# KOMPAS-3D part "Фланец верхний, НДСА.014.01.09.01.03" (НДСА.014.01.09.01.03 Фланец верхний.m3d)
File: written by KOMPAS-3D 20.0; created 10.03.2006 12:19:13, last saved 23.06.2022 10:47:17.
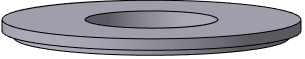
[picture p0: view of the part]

Document properties: Автор: Устинов А.В.; Организация: ЭСТО-Вакуум; Полное имя файла: C:\Users\cherbakova\Desktop\PLM\НДСА.014.01.09.01.03 Фланец верхний.m3d

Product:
- Part/product: Фланец верхний  | designation НДСА.014.01.09.01.03
    Материал: Сталь 20  ГОСТ 1050-88 (density 7820 kg/m3)
    Масса: 1.63755
    additional columns: <item xmlns="http://appius.ru/pdm" xmlns:xs="http://www.w3.org/2001/XMLSchema" x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; <item xmlns="http://appius.ru/pdm" xmlns:xs="http://www.w3.org/2001/XMLSchema" x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; <item xmlns="http://appius.ru/pdm" xmlns:xs="http://www.w3.org/2001/XMLSchema" x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; <item xmlns="http://appius.ru/pdm" xmlns:xs="http://www.w3.org/2001/XMLSchema" x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; <item xmlns="http://appius.ru/pdm" xmlns:xs="http://www.w3.org/2001/XMLSchema" x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; <item xmlns="http://appius.ru/pdm" xmlns:xs="http://www.w3.org/2001/XMLSchema" x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
    source file: НДСА.014.01.09.01.03 Фланец верхний.CDW

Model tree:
1. Плоскость XY
2. Плоскость ZX
3. Плоскость ZY
4. Начало координат
5. Эскиз:1
6. Операция вращения:1  (labels: Сталь 20  ГОСТ 1050-88)
     Угол 1 = 360

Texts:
  НДСА.014.01.09.01.03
